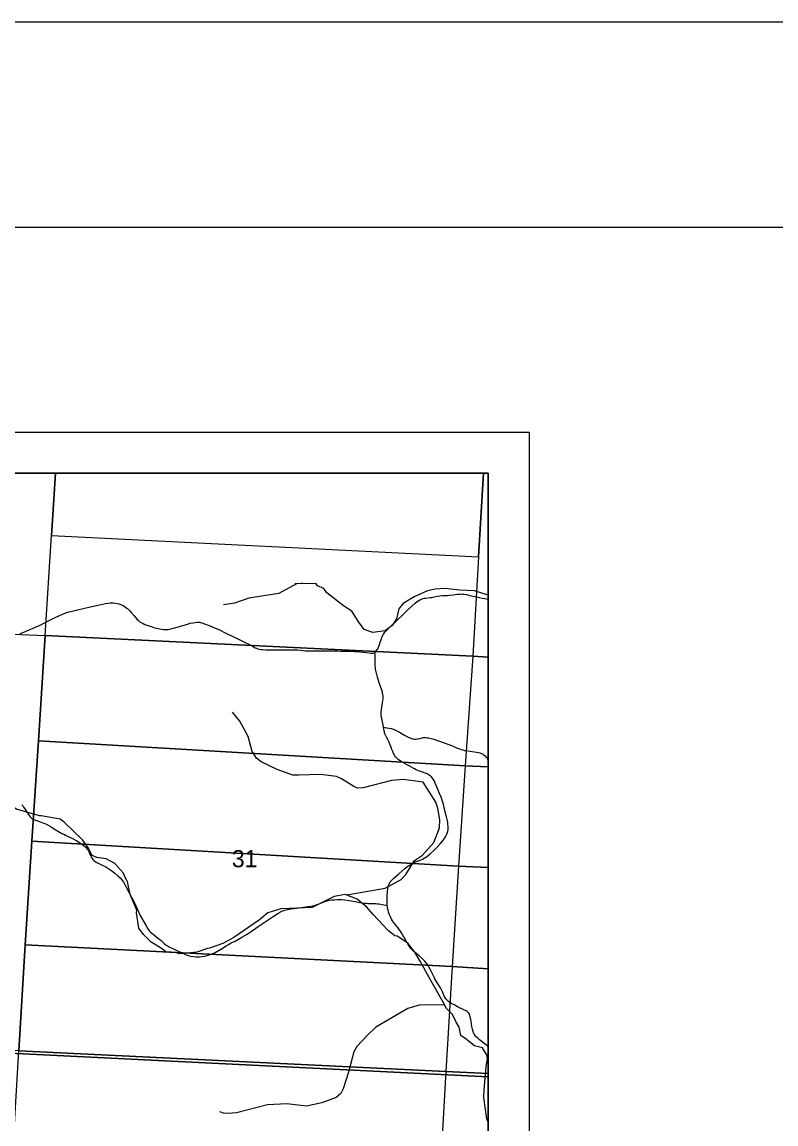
# Model space of a CAD drawing. Extents: x -2.1 to 31.9, y 6.3 to 28.3.
# Drawn here: x 5.698 to 7.536, y 25.658 to 28.344 of the extents above; entities that cross this region are included whole.
import ezdxf

# ---------------------------------------------------------------- set-up
doc = ezdxf.new("R2010")
doc.units = 0
for name, color, linetype in [('Default', 7, 'Continuous'), ('GM_X_County_Road', 7, 'Continuous'), ('GM_X_Minor_River', 7, 'Continuous'), ('GM_X_Section', 7, 'Continuous'), ('GM_X_Section_Text', 7, 'Continuous'), ('GM_X_Township_Road', 7, 'Continuous'), ('SH_Border', 7, 'Continuous'), ('SH_Cut_Line', 7, 'Continuous'), ('SH_Data', 7, 'Continuous')]:
    doc.layers.add(name, color=color, linetype=linetype)

msp = doc.modelspace()

# ---------------------------------------------------------------- linework, layer by layer
at = {"layer": 'Default'}
for points in [[(4.6286, 25.8765), (5.5694, 25.8349), (6.8344, 25.7721), (6.8344, 27.244), (4.7331, 27.244)], [(6.8344, 20.444), (6.8344, 25.7721), (5.5694, 25.8349), (4.6286, 25.8765), (4.6032, 25.4816), (4.5667, 24.9084), (4.5473, 24.5954), (4.4901, 23.6442), (4.4651, 23.2405)]]:
    msp.add_lwpolyline(points, dxfattribs=at)
for points in [[(5.7794, 27.244), (4.7272, 27.244), (4.7032, 26.892), (5.7545, 26.8487), (5.7699, 27.0924)], [(6.8232, 27.244), (5.7794, 27.244), (5.7699, 27.0924), (6.8106, 27.04)], [(6.8344, 26.7954), (6.8344, 27.244), (6.8232, 27.244), (6.8106, 27.04), (6.7966, 26.7978)], [(6.8344, 26.5281), (6.8344, 26.7954), (6.7966, 26.7978), (6.7783, 26.5307)], [(6.8344, 26.2825), (6.8344, 26.5281), (6.7783, 26.5307), (6.7623, 26.2864)], [(6.8344, 26.0359), (6.8344, 26.2825), (6.7623, 26.2864), (6.7462, 26.0413)], [(6.8344, 25.7803), (6.8344, 26.0359), (6.7462, 26.0413), (6.7308, 25.7856)], [(6.8344, 24.7715), (6.8344, 25.7803), (6.7308, 25.7856), (6.674, 24.7794)]]:
    msp.add_lwpolyline(points, close=True, dxfattribs=at)
at = {"layer": 'GM_X_County_Road'}
for points in [[(5.6934, 26.8536), (5.7027, 26.8569), (5.7154, 26.862), (5.7236, 26.8654), (5.7325, 26.8694), (5.7418, 26.8739), (5.754, 26.8802), (5.766, 26.8862), (5.7787, 26.8923), (5.7967, 26.9004), (5.8023, 26.9027), (5.8073, 26.9044), (5.812, 26.9058), (5.8166, 26.907), (5.833, 26.9108), (5.8609, 26.9174), (5.8798, 26.9219), (5.9015, 26.9265), (5.9072, 26.9275), (5.9125, 26.9281), (5.9163, 26.9283), (5.9202, 26.9281), (5.925, 26.9275), (5.9297, 26.9268), (5.9343, 26.9256), (5.9387, 26.924), (5.9428, 26.9221), (5.947, 26.9197), (5.951, 26.917), (5.9548, 26.9141), (5.9581, 26.9113), (5.9609, 26.9085), (5.9643, 26.9048), (5.9711, 26.8964), (5.9755, 26.8912), (5.9789, 26.8875), (5.9807, 26.8857), (5.9828, 26.8839), (5.9862, 26.8813), (5.9896, 26.8793), (5.9931, 26.8774), (5.9975, 26.8755), (6.0046, 26.8728), (6.0127, 26.8701), (6.0216, 26.8674), (6.03, 26.8654), (6.0379, 26.8639), (6.0428, 26.8634), (6.0461, 26.8632), (6.0495, 26.8631), (6.0538, 26.8634), (6.0586, 26.8641), (6.064, 26.8653), (6.0765, 26.8689), (6.1014, 26.8764), (6.108, 26.8782), (6.1149, 26.8797), (6.1199, 26.8804), (6.1248, 26.8808), (6.1273, 26.8808), (6.1295, 26.8807), (6.1318, 26.8804), (6.134, 26.88), (6.1367, 26.8793), (6.1407, 26.878), (6.1454, 26.8763), (6.154, 26.873), (6.1657, 26.8681), (6.1791, 26.8619), (6.1948, 26.8544), (6.2204, 26.8421), (6.2438, 26.8308), (6.2478, 26.8288), (6.2516, 26.8269), (6.2548, 26.8251), (6.2636, 26.82), (6.2665, 26.8185), (6.2695, 26.8172), (6.2728, 26.816), (6.2761, 26.8151), (6.2798, 26.8145), (6.2839, 26.814), (6.2922, 26.8136), (6.3048, 26.8132), (6.3274, 26.8138), (6.3369, 26.8138), (6.3479, 26.8132), (6.3633, 26.8132), (6.3695, 26.8131), (6.3762, 26.8128), (6.3889, 26.8112), (6.3956, 26.8108), (6.4024, 26.811), (6.4148, 26.8113), (6.4312, 26.8111), (6.4442, 26.8112), (6.4517, 26.8111), (6.465, 26.8108), (6.4752, 26.8106), (6.4888, 26.8105), (6.4984, 26.8102), (6.5081, 26.8097), (6.5174, 26.8091), (6.5291, 26.8079), (6.5384, 26.8067), (6.5487, 26.8057), (6.5528, 26.8057), (6.556, 26.806), (6.5578, 26.8069), (6.5602, 26.8092), (6.5624, 26.8117), (6.564, 26.814), (6.5653, 26.8163), (6.5663, 26.8187), (6.5676, 26.822), (6.5733, 26.8386), (6.5748, 26.8428), (6.5762, 26.8459), (6.5791, 26.8514), (6.5807, 26.8539), (6.5826, 26.8564), (6.587, 26.8612), (6.5965, 26.8706), (6.6277, 26.9005), (6.6394, 26.9115), (6.6565, 26.9275), (6.6613, 26.9314), (6.665, 26.9338), (6.6677, 26.9353), (6.6701, 26.9364), (6.673, 26.9375), (6.6758, 26.9384), (6.6794, 26.9392), (6.6825, 26.9396), (6.6926, 26.9407), (6.6973, 26.9413), (6.7024, 26.9423), (6.7115, 26.9442), (6.7162, 26.945), (6.7227, 26.9456), (6.7313, 26.9458), (6.7348, 26.9461), (6.7392, 26.9465), (6.7492, 26.9478), (6.7586, 26.949), (6.7641, 26.9495), (6.769, 26.9496), (6.7722, 26.9495), (6.7756, 26.9491), (6.7818, 26.9481), (6.7896, 26.9462), (6.8068, 26.9424), (6.8127, 26.9412), (6.8194, 26.9398), (6.8259, 26.9384), (6.8344, 26.9366)], [(6.5791, 26.6247), (6.5775, 26.6336), (6.5756, 26.6417), (6.5743, 26.6495), (6.5738, 26.6532), (6.5737, 26.6569), (6.5738, 26.661), (6.5746, 26.6691), (6.5759, 26.6777), (6.5771, 26.6851), (6.5777, 26.6896), (6.578, 26.6936), (6.578, 26.6975), (6.578, 26.701), (6.5776, 26.7044), (6.5771, 26.7074), (6.5765, 26.7108), (6.5752, 26.7155), (6.5698, 26.7308), (6.5663, 26.7414), (6.5646, 26.7467), (6.5627, 26.7537), (6.5611, 26.7602), (6.5599, 26.7664), (6.5593, 26.7705), (6.5589, 26.7752), (6.5587, 26.7798), (6.5586, 26.7847), (6.5587, 26.7955), (6.5588, 26.8037), (6.5578, 26.8069)], [(6.6521, 26.0791), (6.6495, 26.0815), (6.6473, 26.0837), (6.6452, 26.0864), (6.6425, 26.0899), (6.6395, 26.0948), (6.6366, 26.1001), (6.6348, 26.1034), (6.631, 26.1104), (6.6291, 26.1136), (6.6275, 26.1161), (6.6231, 26.1234), (6.6203, 26.1275), (6.6175, 26.1316), (6.6137, 26.1365), (6.6058, 26.1466), (6.6013, 26.1529), (6.599, 26.1566), (6.5961, 26.1622), (6.5939, 26.1673), (6.5916, 26.1738), (6.5903, 26.1787), (6.5892, 26.1835), (6.5886, 26.1869), (6.5882, 26.1901), (6.588, 26.193), (6.5877, 26.1967), (6.5877, 26.2009), (6.5882, 26.2124), (6.5889, 26.2244), (6.5897, 26.2305), (6.5908, 26.236), (6.5917, 26.2392), (6.5927, 26.2421), (6.5941, 26.2449), (6.5958, 26.2477), (6.5977, 26.2503), (6.6, 26.2529), (6.6037, 26.2563), (6.6163, 26.2674), (6.6311, 26.2804), (6.636, 26.2843), (6.6401, 26.2872), (6.6439, 26.2896), (6.648, 26.292), (6.6523, 26.2942), (6.6588, 26.2971), (6.667, 26.3003), (6.6739, 26.3033), (6.6779, 26.3052), (6.6813, 26.3071), (6.6847, 26.3095), (6.6882, 26.312), (6.6933, 26.3164), (6.7018, 26.3246), (6.7115, 26.3342), (6.7178, 26.341), (6.7226, 26.3467), (6.727, 26.3526), (6.7304, 26.3578), (6.7329, 26.3627), (6.7346, 26.3667), (6.7359, 26.3708), (6.7364, 26.3729), (6.7367, 26.3749), (6.7371, 26.3792), (6.737, 26.3834), (6.7364, 26.3882), (6.7358, 26.3923), (6.7349, 26.3965), (6.7326, 26.406), (6.7289, 26.4218), (6.7253, 26.4366), (6.7237, 26.4419), (6.7223, 26.4465), (6.721, 26.4501), (6.7194, 26.454), (6.7156, 26.4634), (6.7109, 26.4752), (6.7055, 26.4887), (6.7034, 26.4932), (6.701, 26.4974), (6.6976, 26.5017), (6.6958, 26.5036), (6.6938, 26.5054), (6.6907, 26.5078), (6.6881, 26.5094), (6.6861, 26.5106), (6.6838, 26.5117), (6.6809, 26.5127), (6.6702, 26.5166), (6.6666, 26.518), (6.6629, 26.5195), (6.6591, 26.5212), (6.655, 26.5232), (6.6462, 26.5279), (6.6381, 26.5321), (6.6247, 26.5393), (6.6194, 26.5426), (6.6159, 26.5452), (6.6122, 26.5486), (6.6093, 26.5518), (6.6067, 26.5554), (6.6051, 26.558), (6.6035, 26.5611), (6.6016, 26.5653), (6.5995, 26.5708), (6.5968, 26.5781), (6.5945, 26.5838), (6.592, 26.5897), (6.5894, 26.5951), (6.5867, 26.6003), (6.5843, 26.6053), (6.5826, 26.6089), (6.5818, 26.6109), (6.5812, 26.6133), (6.5806, 26.6158), (6.5791, 26.6247)], [(6.8344, 25.8455), (6.8302, 25.8496), (6.8249, 25.854), (6.8197, 25.8581), (6.8133, 25.8631), (6.8089, 25.8667), (6.8053, 25.8701), (6.8036, 25.872), (6.8021, 25.8739), (6.8009, 25.8754), (6.8, 25.8771), (6.7987, 25.8799), (6.7975, 25.8832), (6.7961, 25.8885), (6.7947, 25.8952), (6.7926, 25.9081), (6.7919, 25.9124), (6.7908, 25.9178), (6.7897, 25.922), (6.7887, 25.9248), (6.7877, 25.9269), (6.7864, 25.9289), (6.785, 25.9304), (6.7832, 25.9318), (6.7811, 25.9331), (6.7748, 25.9362), (6.7599, 25.9432), (6.7527, 25.9469), (6.7445, 25.9515), (6.7409, 25.954), (6.7379, 25.9562), (6.7341, 25.9594), (6.7321, 25.9616), (6.7305, 25.9639), (6.7274, 25.9695), (6.7227, 25.9795), (6.7196, 25.9862), (6.718, 25.9894), (6.7164, 25.9923), (6.7126, 25.9988), (6.7067, 26.0075), (6.7043, 26.0116), (6.7023, 26.0157), (6.6954, 26.0303), (6.6907, 26.0391), (6.6869, 26.0454), (6.6833, 26.0504), (6.6794, 26.0551), (6.6737, 26.0607), (6.6663, 26.0673), (6.6624, 26.0705), (6.6583, 26.074), (6.6527, 26.0785), (6.6521, 26.0791)]]:
    msp.add_lwpolyline(points, dxfattribs=at)
at = {"layer": 'GM_X_Minor_River'}
for points in [[(6.3672, 26.9744), (6.3242, 26.9506), (6.2505, 26.9396), (6.2158, 26.9274), (6.1888, 26.923)], [(6.8344, 26.9469), (6.8342, 26.9469), (6.8009, 26.9571), (6.7654, 26.9589), (6.7287, 26.963), (6.7049, 26.9611), (6.6868, 26.9576), (6.6543, 26.9427), (6.6275, 26.9267), (6.6165, 26.9137), (6.6161, 26.9099), (6.6112, 26.8894), (6.5999, 26.8726), (6.5829, 26.8597), (6.5599, 26.8562), (6.5531, 26.8554), (6.5319, 26.863), (6.5194, 26.8808), (6.502, 26.9077), (6.4815, 26.921), (6.4414, 26.9528), (6.4335, 26.9627), (6.418, 26.9695), (6.4153, 26.9741), (6.3824, 26.9755), (6.379, 26.9755), (6.3632, 26.974)], [(5.8691, 26.3117), (5.86, 26.3303), (5.8452, 26.3505), (5.8005, 26.3933), (5.7911, 26.4005), (5.7446, 26.4084), (5.7408, 26.4084), (5.6841, 26.4253), (5.6557, 26.442), (5.6338, 26.4613), (5.6069, 26.5054), (5.5906, 26.5251), (5.5906, 26.5293), (5.5595, 26.5809), (5.5489, 26.6014), (5.5493, 26.6409), (5.5526, 26.6717), (5.5488, 26.6907), (5.5453, 26.7123)], [(6.4897, 26.216), (6.583, 26.2321), (6.6222, 26.2533), (6.6335, 26.2658), (6.6549, 26.2997), (6.6739, 26.3127), (6.7016, 26.3434), (6.7156, 26.3794), (6.7162, 26.3991), (6.7117, 26.4274), (6.7065, 26.442), (6.6758, 26.4908), (6.6333, 26.4967), (6.6276, 26.4973), (6.5985, 26.4948), (6.5295, 26.4769), (6.5155, 26.4762), (6.5069, 26.4799), (6.4765, 26.4987), (6.4642, 26.5048), (6.4254, 26.5094), (6.3728, 26.5077), (6.3585, 26.5078), (6.3203, 26.5215), (6.2808, 26.5406), (6.2694, 26.5493), (6.2589, 26.5653), (6.2494, 26.602), (6.229, 26.6395), (6.2112, 26.6617)], [(5.955, 26.249), (5.9538, 26.2507), (5.9443, 26.2701), (5.9243, 26.2929), (5.9031, 26.3042), (5.88, 26.3072), (5.8691, 26.3117)], [(6.6692, 26.0528), (6.6559, 26.0768), (6.6385, 26.098), (6.6124, 26.1154), (6.6064, 26.1166), (6.5924, 26.1279), (6.5901, 26.1302), (6.5538, 26.1681), (6.5386, 26.1863), (6.5152, 26.206), (6.4853, 26.217), (6.4589, 26.212), (6.4056, 26.1853), (6.3496, 26.1828), (6.3288, 26.182), (6.2975, 26.1721), (6.2767, 26.1549), (6.214, 26.1122), (6.1872, 26.0977), (6.1547, 26.0858), (6.1501, 26.0851), (6.1244, 26.0767), (6.095, 26.0735), (6.0814, 26.0724), (6.0742, 26.0754), (6.0488, 26.0772), (6.0398, 26.0844), (6.0129, 26.1011), (5.994, 26.1197), (5.9826, 26.1349), (5.9769, 26.1721), (5.9777, 26.1789), (5.9614, 26.2173), (5.955, 26.249)], [(6.8344, 25.6611), (6.8314, 25.6701), (6.8276, 25.6925), (6.8238, 25.7221), (6.8249, 25.7404), (6.8297, 25.7966), (6.8324, 25.8176), (6.8312, 25.8263), (6.8255, 25.835), (6.8202, 25.843), (6.8009, 25.8483), (6.7854, 25.8604), (6.7835, 25.8627), (6.7673, 25.8729), (6.7639, 25.8938), (6.7555, 25.9071), (6.7472, 25.9242), (6.7324, 25.9393), (6.7249, 25.9545), (6.6942, 26.0073), (6.6692, 26.0528)], [(6.7281, 25.948), (6.6659, 25.9469), (6.6382, 25.9387), (6.5607, 25.8936), (6.5405, 25.8743), (6.5145, 25.8467), (6.5069, 25.8338), (6.4937, 25.7837), (6.4806, 25.7432), (6.4753, 25.7322), (6.4638, 25.722), (6.4289, 25.7089), (6.3913, 25.7008), (6.3436, 25.7064), (6.2966, 25.7044), (6.2207, 25.6851), (6.1998, 25.6834), (6.1892, 25.6842), (6.1801, 25.6869)]]:
    msp.add_lwpolyline(points, dxfattribs=at)
at = {"layer": 'GM_X_Section'}
for points in [[(6.8106, 27.04), (6.7966, 26.7978), (5.7545, 26.8487), (5.7699, 27.0924)], [(4.7032, 26.892), (5.7545, 26.8487), (5.7377, 26.5914), (5.7216, 26.3472), (5.7057, 26.0946), (5.6902, 25.8357), (4.6345, 25.8828)], [(6.7966, 26.7978), (6.7783, 26.5307), (5.7377, 26.5914), (5.7545, 26.8487)], [(5.7377, 26.5914), (6.7783, 26.5307), (6.7623, 26.2864), (5.7216, 26.3472)], [(6.7623, 26.2864), (6.7462, 26.0413), (5.7057, 26.0946), (5.7216, 26.3472)], [(5.7057, 26.0946), (6.7462, 26.0413), (6.7308, 25.7856), (5.6902, 25.8357)], [(6.7308, 25.7856), (6.674, 24.7794), (5.6296, 24.8273), (5.6902, 25.8357)]]:
    msp.add_lwpolyline(points, close=True, dxfattribs=at)
at = {"layer": 'GM_X_Township_Road'}
for points in [[(6.5791, 26.6247), (6.5875, 26.6235), (6.5927, 26.6227), (6.5978, 26.6216), (6.6005, 26.6208), (6.6033, 26.6199), (6.6065, 26.6186), (6.6129, 26.6155), (6.6181, 26.6129), (6.6307, 26.6054), (6.638, 26.6015), (6.6435, 26.5989), (6.6474, 26.5974), (6.6501, 26.5966), (6.6526, 26.5962), (6.6556, 26.5959), (6.6584, 26.5959), (6.6622, 26.5964), (6.6677, 26.5977), (6.6735, 26.599), (6.6762, 26.5994), (6.6793, 26.5996), (6.6826, 26.5996), (6.6859, 26.5993), (6.6889, 26.5989), (6.6957, 26.5974), (6.7018, 26.5957), (6.7108, 26.5925), (6.7297, 26.5857), (6.7364, 26.5831)], [(6.7364, 26.5831), (6.747, 26.5791), (6.7575, 26.5748), (6.7648, 26.5718), (6.7684, 26.5705), (6.7722, 26.5693), (6.7765, 26.5683), (6.7857, 26.5669), (6.7956, 26.5655), (6.806, 26.5639), (6.811, 26.563), (6.8138, 26.5622), (6.8163, 26.5615), (6.8183, 26.5606), (6.8204, 26.5596), (6.8224, 26.5584), (6.8247, 26.5567), (6.827, 26.5547), (6.8297, 26.5521), (6.8315, 26.5496), (6.833, 26.5471), (6.8343, 26.5441), (6.8344, 26.5435)], [(5.6974, 26.4359), (5.6998, 26.4329), (5.7019, 26.43), (5.7049, 26.4255), (5.7089, 26.419), (5.7127, 26.4126), (5.715, 26.4092), (5.7175, 26.4063), (5.7202, 26.4037), (5.7228, 26.4018), (5.7245, 26.4007), (5.7263, 26.3998), (5.7287, 26.3988), (5.7309, 26.3979), (5.7379, 26.3955), (5.7447, 26.3932), (5.7488, 26.3917), (5.7533, 26.3898), (5.7619, 26.3857), (5.7674, 26.3829), (5.7725, 26.3799), (5.7868, 26.3705), (5.7906, 26.3683), (5.7949, 26.3659), (5.7995, 26.3637), (5.8039, 26.3617), (5.8089, 26.3594), (5.8195, 26.3543), (5.8314, 26.3476), (5.8406, 26.342), (5.8456, 26.3383), (5.8503, 26.3347), (5.8533, 26.332), (5.8562, 26.3287), (5.8588, 26.3252), (5.8605, 26.322), (5.8627, 26.3171), (5.8653, 26.3113), (5.8668, 26.3077), (5.8687, 26.3045), (5.8707, 26.302), (5.8732, 26.2996), (5.8766, 26.2974), (5.8805, 26.2952), (5.892, 26.2896), (5.902, 26.2842), (5.9097, 26.2794), (5.9167, 26.2747), (5.9244, 26.2688), (5.9315, 26.2628), (5.9368, 26.2575), (5.9409, 26.2529), (5.9428, 26.2503), (5.9449, 26.2473), (5.9483, 26.2415), (5.952, 26.2346), (5.958, 26.2226), (5.9653, 26.2092), (5.9685, 26.2033), (5.9718, 26.1967), (5.9793, 26.1804), (5.9871, 26.1645), (5.9927, 26.1541), (5.9996, 26.1423), (6.005, 26.1332), (6.0069, 26.1302), (6.0088, 26.1278), (6.0109, 26.1255), (6.0143, 26.1226), (6.0215, 26.1168), (6.0284, 26.1114), (6.0317, 26.1088), (6.036, 26.1053), (6.0409, 26.1009), (6.0456, 26.0968), (6.0497, 26.0937), (6.0527, 26.0918), (6.0563, 26.0898), (6.0707, 26.0832), (6.0843, 26.0764), (6.0928, 26.0721), (6.0979, 26.0698), (6.1031, 26.0679), (6.1062, 26.0671), (6.1098, 26.0664), (6.1162, 26.0655), (6.1213, 26.0651), (6.1258, 26.0651), (6.1303, 26.0653), (6.1368, 26.066), (6.1431, 26.067), (6.1472, 26.0678), (6.1515, 26.0688), (6.1566, 26.0705), (6.1631, 26.073), (6.1689, 26.0758), (6.1842, 26.0848), (6.1957, 26.092), (6.2016, 26.0954), (6.2079, 26.0989), (6.2156, 26.1028), (6.2354, 26.1136), (6.2408, 26.1168), (6.2466, 26.1203), (6.2568, 26.1268), (6.274, 26.1386), (6.2932, 26.1524), (6.31, 26.1637), (6.3213, 26.1709), (6.3262, 26.1738), (6.3299, 26.1756), (6.3328, 26.177), (6.3358, 26.1781), (6.3387, 26.1791), (6.342, 26.1799), (6.345, 26.1806), (6.3491, 26.1814), (6.3536, 26.1821), (6.3621, 26.1832), (6.3843, 26.1859), (6.3947, 26.1874), (6.4026, 26.1886), (6.4064, 26.1894), (6.4097, 26.1901), (6.4134, 26.1911), (6.417, 26.1923), (6.4222, 26.1942), (6.4361, 26.1997), (6.442, 26.2017), (6.4469, 26.2029), (6.4524, 26.2038), (6.4593, 26.2044), (6.4674, 26.2048), (6.4717, 26.2048), (6.4779, 26.2046), (6.4848, 26.2039), (6.4952, 26.2024), (6.51, 26.1998), (6.5259, 26.1971), (6.5332, 26.1961), (6.5381, 26.1956), (6.5418, 26.1953), (6.5474, 26.195), (6.5524, 26.1949), (6.5604, 26.1948), (6.564, 26.1946), (6.5674, 26.1943), (6.5716, 26.1936), (6.5801, 26.1918), (6.5882, 26.1901)]]:
    msp.add_lwpolyline(points, dxfattribs=at)
at = {"layer": 'SH_Border'}
msp.add_lwpolyline([(-0.5656, 27.844), (31.4344, 27.844), (31.4344, 6.844), (-0.5656, 6.844)], close=True, dxfattribs=at)
at = {"layer": 'SH_Cut_Line'}
msp.add_lwpolyline([(-2.0656, 6.344), (31.9344, 6.344), (31.9344, 28.344), (-2.0656, 28.344)], close=True, dxfattribs=at)
msp.add_lwpolyline([(6.8344, 20.444), (6.8344, 27.244), (0.0344, 27.244), (0.0344, 20.444)], dxfattribs=at)
at = {"layer": 'SH_Data'}
for p, q in [((-0.0656, 27.344), (6.9344, 27.344)), ((6.9344, 27.344), (6.9344, 20.344)), ((0.0344, 27.244), (6.8344, 27.244)), ((6.8344, 27.244), (6.8344, 20.444))]:
    msp.add_line(p, q, dxfattribs=at)

# ---------------------------------------------------------------- texts
at = {"layer": 'GM_X_Section_Text'}
msp.add_text('31', height=0.04186, rotation=0, dxfattribs=at).set_placement((6.2095, 26.2834))

doc.saveas('drawing.dxf')
